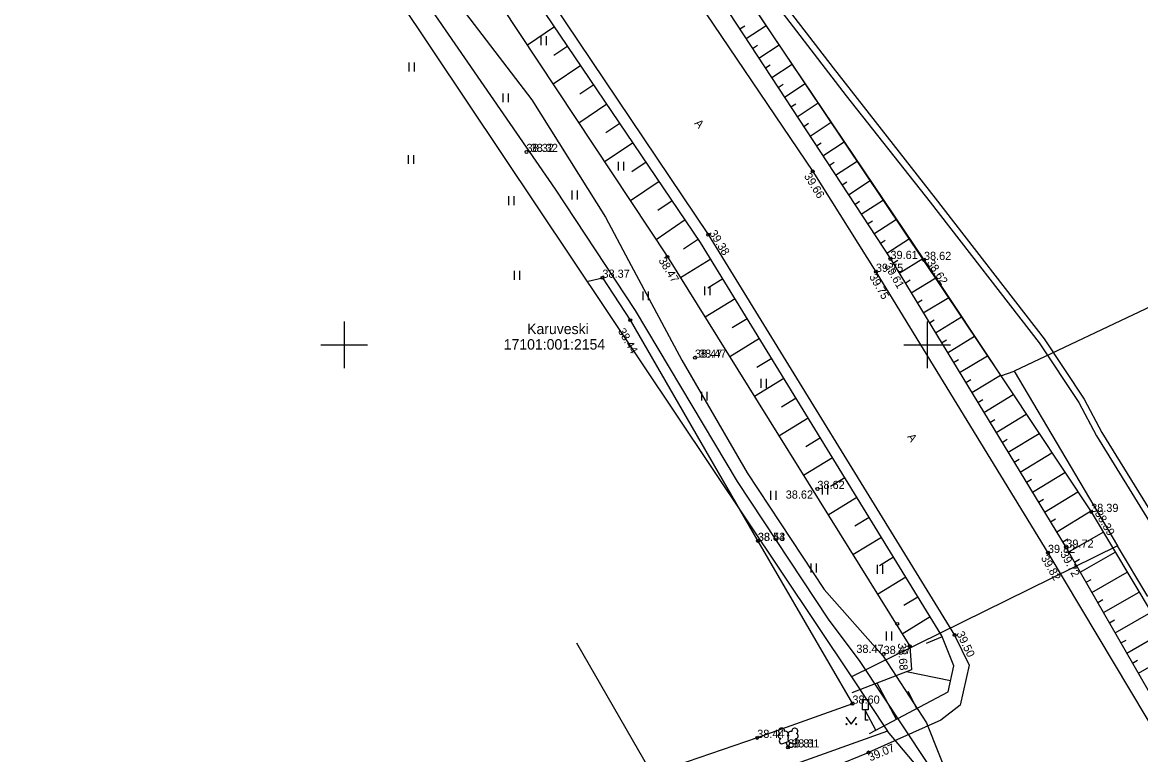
# Model space of a CAD drawing. Extents: x 627548 to 628052, y 6467984 to 6468802.
# Drawn here: x 627722.4 to 627818.3, y 6468464.9 to 6468527.7 of the extents above; entities that cross this region are included whole.
import ezdxf

# ---------------------------------------------------------------- set-up
doc = ezdxf.new("R2010")
doc.units = 0
for name, color, linetype in [('AED', 7, 'Continuous'), ('HALJASTUS', 7, 'Continuous'), ('KORGUS-EH2000', 7, 'Continuous'), ('KPKAABEL', 7, 'Continuous'), ('LIIKLUS', 7, 'Continuous'), ('MOOTKORG-EH2000', 7, 'Continuous'), ('MOOTMPUNKT', 7, 'Continuous'), ('MPKAABEL', 7, 'Continuous'), ('MPOHULIIN', 7, 'Continuous'), ('PIIR', 7, 'Continuous'), ('PUU', 7, 'Continuous'), ('RELJEEF', 7, 'Continuous'), ('SITRASS', 7, 'Continuous'), ('TEE', 7, 'Continuous'), ('VORK', 7, 'Continuous')]:
    doc.layers.add(name, color=color, linetype=linetype)

msp = doc.modelspace()

# ---------------------------------------------------------------- linework, layer by layer
at = {"layer": 'AED'}
for points in [[(627770.937, 6468505.458), (627772.148, 6468505.761), (627774.528, 6468502.126), (627785.471, 6468483.185), (627793.589, 6468469.234)], [(627793.589, 6468469.234), (627785.422, 6468466.301), (627773.403, 6468462.19), (627765.44, 6468459.471)]]:
    msp.add_lwpolyline(points, dxfattribs=at)
at = {"layer": 'HALJASTUS'}
for p, q in [((627766.874, 6468526.485), (627766.874, 6468525.724)), ((627767.329, 6468526.485), (627767.329, 6468525.724)), ((627755.548, 6468524.212), (627755.548, 6468523.45)), ((627756.003, 6468524.212), (627756.003, 6468523.45)), ((627763.616, 6468521.569), (627763.616, 6468520.808)), ((627764.071, 6468521.569), (627764.071, 6468520.808)), ((627755.481, 6468516.283), (627755.481, 6468515.522)), ((627755.936, 6468516.283), (627755.936, 6468515.522)), ((627773.488, 6468515.716), (627773.488, 6468514.955)), ((627773.943, 6468515.716), (627773.943, 6468514.955)), ((627764.09, 6468512.759), (627764.09, 6468511.998)), ((627764.545, 6468512.759), (627764.545, 6468511.998)), ((627769.513, 6468513.233), (627769.513, 6468512.472)), ((627769.968, 6468513.233), (627769.968, 6468512.472)), ((627764.576, 6468506.357), (627764.576, 6468505.595)), ((627765.031, 6468506.357), (627765.031, 6468505.595)), ((627780.911, 6468505.024), (627780.911, 6468504.263)), ((627781.366, 6468505.024), (627781.366, 6468504.263)), ((627775.626, 6468504.595), (627775.626, 6468503.833)), ((627776.081, 6468504.595), (627776.081, 6468503.833)), ((627785.745, 6468497.09), (627785.745, 6468496.329)), ((627786.2, 6468497.09), (627786.2, 6468496.329)), ((627780.643, 6468495.988), (627780.643, 6468495.227)), ((627781.098, 6468495.988), (627781.098, 6468495.227)), ((627791, 6468487.94), (627791, 6468487.179)), ((627791.455, 6468487.94), (627791.455, 6468487.179)), ((627786.556, 6468487.484), (627786.556, 6468486.723)), ((627787.011, 6468487.484), (627787.011, 6468486.723)), ((627790.013, 6468481.249), (627790.013, 6468480.488)), ((627790.468, 6468481.249), (627790.468, 6468480.488)), ((627795.71, 6468481.138), (627795.71, 6468480.376)), ((627796.165, 6468481.138), (627796.165, 6468480.376)), ((627796.474, 6468475.416), (627796.474, 6468474.655)), ((627796.929, 6468475.416), (627796.929, 6468474.655)), ((627793.019, 6468468.081), (627793.483, 6468467.474)), ((627793.483, 6468467.474), (627793.928, 6468468.081))]:
    msp.add_line(p, q, dxfattribs=at)
for centre in [(627793.081, 6468467.474), (627793.91, 6468467.474)]:
    msp.add_circle(centre, 0.055, dxfattribs=at)
at = {"layer": 'KORGUS-EH2000'}
for centre in [(627790.19, 6468514.887), (627781.22, 6468509.457), (627777.72, 6468507.557), (627774.53, 6468502.127), (627802.36, 6468475.117), (627798.51, 6468474.167), (627794.97, 6468465.057)]:
    msp.add_circle(centre, 0.125, dxfattribs=at)
at = {"layer": 'KPKAABEL'}
msp.add_lwpolyline([(627783.664, 6468533.605), (627793.043, 6468521.367), (627800.254, 6468512.234), (627809.598, 6468500.188), (627812.996, 6468495.066), (627814.512, 6468492.199), (627820.805, 6468482.012), (627827.375, 6468470.727), (627831.316, 6468464.148), (627838.215, 6468452.395), (627843.543, 6468447.449), (627852.07, 6468429.637), (627862.617, 6468434.004), (627863.434, 6468433.738), (627868.465, 6468427.605)], dxfattribs=at)
at = {"layer": 'LIIKLUS'}
for points in [[(627794.439, 6468469.559), (627794.439, 6468468.709)], [(627794.939, 6468469.559), (627794.439, 6468469.559)], [(627794.939, 6468469.559), (627794.939, 6468468.709)], [(627794.939, 6468468.709), (627794.439, 6468468.709)], [(627794.689, 6468468.709), (627794.689, 6468467.809)], [(627794.939, 6468467.809), (627794.689, 6468467.809)]]:
    msp.add_lwpolyline(points, dxfattribs=at)
at = {"layer": 'MOOTMPUNKT'}
for centre in [(627765.636, 6468516.549), (627796.852, 6468507.373), (627799.726, 6468507.289), (627772.148, 6468505.761), (627795.603, 6468506.268), (627780.081, 6468498.904), (627790.584, 6468487.647), (627814.065, 6468485.677), (627785.486, 6468483.195), (627810.358, 6468482.16), (627811.934, 6468482.612), (627797.433, 6468476.083), (627796.265, 6468473.492), (627793.589, 6468469.234), (627785.422, 6468466.301), (627788.07, 6468465.478)]:
    msp.add_circle(centre, 0.125, dxfattribs=at)
at = {"layer": 'MPKAABEL'}
msp.add_lwpolyline([(627775.609, 6468546.285), (627774.98, 6468546.789), (627774.719, 6468546.18), (627774.691, 6468545.898), (627776.109, 6468544.039), (627784.09, 6468533.941), (627791.949, 6468523.77), (627800.68, 6468512.578), (627810.039, 6468500.512), (627813.461, 6468495.352), (627814.988, 6468492.48), (627821.281, 6468482.301), (627827.852, 6468471.012), (627838.641, 6468452.75), (627843.988, 6468447.781), (627852.328, 6468430.34), (627859.234, 6468424.973)], dxfattribs=at)
at = {"layer": 'MPOHULIIN'}
msp.add_lwpolyline([(627776.772, 6468462.547), (627769.965, 6468474.421)], dxfattribs=at)
at = {"layer": 'PIIR'}
for p, q in [((627739.66, 6468596.76), (627806.32, 6468497.36)), ((627746.88, 6468541.25), (627793.5, 6468471.53)), ((627819.793, 6468503.596), (627807.45, 6468497.75)), ((627806.32, 6468497.36), (627807.45, 6468497.75)), ((627807.45, 6468497.75), (627816.33, 6468482.77)), ((627816.33, 6468482.77), (627793.5, 6468471.53)), ((627818.92, 6468478.42), (627816.33, 6468482.77)), ((627793.5, 6468471.53), (627796.61, 6468466.88)), ((627796.61, 6468466.88), (627730.27, 6468443.22)), ((627801.28, 6468461.34), (627796.61, 6468466.88))]:
    msp.add_line(p, q, dxfattribs=at)
at = {"layer": 'PUU'}
for p, q in [((627787.63, 6468465.813), (627788.075, 6468465.988)), ((627788.07, 6468465.478), (627787.895, 6468465.918)), ((627788.07, 6468465.478), (627788.25, 6468465.918)), ((627788.075, 6468465.988), (627788.515, 6468465.808)), ((627788.45, 6468465.478), (627788.07, 6468465.478))]:
    msp.add_line(p, q, dxfattribs=at)
msp.add_lwpolyline([(627788.075, 6468466.483), (627788.055, 6468466.408), (627788.055, 6468466.388), (627788.065, 6468466.358), (627788.085, 6468466.323), (627788.09, 6468466.303), (627788.075, 6468466.268), (627788.05, 6468466.218), (627788.045, 6468466.193), (627788.05, 6468466.178), (627788.06, 6468466.148), (627788.095, 6468466.088), (627788.1, 6468466.068), (627788.095, 6468466.048), (627788.08, 6468466.013), (627788.075, 6468465.988)], dxfattribs=at)
for centre, radius, start, end in [((627787.439, 6468466.481), 0.224, 111.43041, 274.49868), ((627787.513, 6468466.892), 0.256, 111.50269, 232.51731), ((627787.513, 6468466.892), 0.256, 350.48556, 111.50017), ((627787.848, 6468466.642), 0.224, 308.50412, 111.57247), ((627788.074, 6468466.245), 0.237, 66.76552, 111.50149), ((627788.311, 6468466.637), 0.225, 67.7016, 230.51262), ((627788.649, 6468466.883), 0.256, 67.6168, 188.63142), ((627788.716, 6468466.471), 0.224, 264.6183, 67.68657), ((627788.649, 6468466.883), 0.256, 306.59966, 67.61428), ((627787.544, 6468466.036), 0.237, 111.50143, 291.50036), ((627788.605, 6468466.028), 0.237, 247.61661, 67.61554)]:
    msp.add_arc(centre, radius, start, end, dxfattribs=at)
at = {"layer": 'RELJEEF'}
for p, q in [((627768.047, 6468527.281), (627765.71, 6468525.699)), ((627783.932, 6468527.108), (627784.351, 6468527.382)), ((627784.48, 6468526.272), (627786.183, 6468527.387)), ((627769.168, 6468525.625), (627767.991, 6468524.828)), ((627785.028, 6468525.435), (627785.446, 6468525.709)), ((627785.575, 6468524.598), (627787.301, 6468525.728)), ((627786.123, 6468523.762), (627786.542, 6468524.035)), ((627786.671, 6468522.925), (627788.419, 6468524.069)), ((627770.289, 6468523.969), (627767.918, 6468522.364)), ((627771.41, 6468522.312), (627770.216, 6468521.504)), ((627787.219, 6468522.088), (627787.637, 6468522.362)), ((627787.766, 6468521.252), (627789.537, 6468522.41)), ((627772.531, 6468520.656), (627770.127, 6468519.028)), ((627788.314, 6468520.415), (627788.732, 6468520.689)), ((627788.862, 6468519.578), (627790.654, 6468520.752)), ((627773.652, 6468519), (627772.442, 6468518.18)), ((627789.41, 6468518.742), (627789.828, 6468519.016)), ((627789.957, 6468517.905), (627791.772, 6468519.093)), ((627774.773, 6468517.343), (627772.335, 6468515.693)), ((627790.505, 6468517.068), (627790.923, 6468517.342)), ((627791.053, 6468516.232), (627792.89, 6468517.434)), ((627775.894, 6468515.687), (627774.667, 6468514.856)), ((627791.6, 6468515.395), (627792.019, 6468515.669)), ((627792.148, 6468514.558), (627794.007, 6468515.776)), ((627777.015, 6468514.031), (627774.543, 6468512.358)), ((627792.696, 6468513.722), (627793.114, 6468513.996)), ((627793.244, 6468512.885), (627795.125, 6468514.117)), ((627778.136, 6468512.374), (627776.892, 6468511.532)), ((627793.791, 6468512.048), (627794.21, 6468512.322)), ((627794.339, 6468511.212), (627796.243, 6468512.458)), ((627779.257, 6468510.718), (627776.752, 6468509.022)), ((627794.887, 6468510.375), (627795.305, 6468510.649)), ((627795.434, 6468509.538), (627797.361, 6468510.799)), ((627780.378, 6468509.062), (627779.114, 6468508.206)), ((627795.982, 6468508.702), (627796.4, 6468508.976)), ((627796.53, 6468507.865), (627798.478, 6468509.141)), ((627781.436, 6468507.365), (627778.835, 6468505.77)), ((627797.066, 6468507.021), (627797.493, 6468507.281)), ((627797.586, 6468506.167), (627799.639, 6468507.418)), ((627782.482, 6468505.66), (627781.187, 6468504.866)), ((627798.107, 6468505.313), (627798.534, 6468505.573)), ((627798.627, 6468504.459), (627800.747, 6468505.75)), ((627783.527, 6468503.955), (627780.949, 6468502.374)), ((627799.667, 6468502.751), (627801.853, 6468504.083)), ((627799.147, 6468503.605), (627799.574, 6468503.865)), ((627784.573, 6468502.25), (627783.289, 6468501.463)), ((627800.187, 6468501.897), (627800.614, 6468502.157)), ((627800.708, 6468501.043), (627802.96, 6468502.415)), ((627785.618, 6468500.545), (627783.063, 6468498.978)), ((627801.228, 6468500.189), (627801.655, 6468500.449)), ((627801.748, 6468499.335), (627804.066, 6468500.747)), ((627786.664, 6468498.84), (627785.392, 6468498.06)), ((627802.268, 6468498.481), (627802.695, 6468498.741)), ((627802.788, 6468497.627), (627805.173, 6468499.079)), ((627803.829, 6468495.919), (627806.28, 6468497.411)), ((627787.709, 6468497.135), (627785.177, 6468495.583)), ((627803.309, 6468496.773), (627803.736, 6468497.033)), ((627788.755, 6468495.43), (627787.495, 6468494.657)), ((627804.349, 6468495.065), (627804.776, 6468495.325)), ((627804.869, 6468494.211), (627807.386, 6468495.744)), ((627789.8, 6468493.725), (627787.292, 6468492.187)), ((627805.389, 6468493.357), (627805.817, 6468493.617)), ((627805.91, 6468492.502), (627808.493, 6468494.076)), ((627806.95, 6468490.794), (627809.599, 6468492.408)), ((627790.846, 6468492.02), (627789.597, 6468491.254)), ((627806.43, 6468491.648), (627806.857, 6468491.909)), ((627807.99, 6468489.086), (627810.706, 6468490.74)), ((627791.891, 6468490.315), (627789.406, 6468488.791)), ((627807.47, 6468489.94), (627807.897, 6468490.2)), ((627792.936, 6468488.61), (627791.7, 6468487.852)), ((627809.031, 6468487.378), (627811.812, 6468489.072)), ((627808.511, 6468488.232), (627808.938, 6468488.492)), ((627793.982, 6468486.905), (627791.52, 6468485.395)), ((627809.551, 6468486.524), (627809.978, 6468486.784)), ((627810.071, 6468485.67), (627812.919, 6468487.405)), ((627811.112, 6468483.962), (627814.025, 6468485.737)), ((627795.027, 6468485.2), (627793.802, 6468484.449)), ((627810.591, 6468484.816), (627811.019, 6468485.076)), ((627812.143, 6468482.248), (627815.1, 6468483.946)), ((627796.073, 6468483.495), (627793.634, 6468482)), ((627811.632, 6468483.108), (627812.059, 6468483.368)), ((627813.138, 6468480.514), (627816.127, 6468482.229)), ((627797.118, 6468481.79), (627795.905, 6468481.046)), ((627812.641, 6468481.381), (627813.074, 6468481.63)), ((627798.164, 6468480.085), (627795.749, 6468478.604)), ((627814.134, 6468478.779), (627817.153, 6468480.513)), ((627813.636, 6468479.647), (627814.07, 6468479.896)), ((627799.209, 6468478.38), (627798.007, 6468477.643)), ((627814.632, 6468477.912), (627815.066, 6468478.161)), ((627815.13, 6468477.045), (627818.18, 6468478.796)), ((627816.126, 6468475.31), (627819.206, 6468477.079)), ((627800.255, 6468476.675), (627797.863, 6468475.208)), ((627815.628, 6468476.178), (627816.061, 6468476.427)), ((627817.121, 6468473.576), (627820.233, 6468475.362)), ((627801.287, 6468474.963), (627799.909, 6468474.409)), ((627816.624, 6468474.443), (627817.057, 6468474.692)), ((627818.117, 6468471.841), (627821.26, 6468473.645)), ((627817.619, 6468472.709), (627818.053, 6468472.958)), ((627802.009, 6468471.184), (627798.225, 6468471.976)), ((627797.357, 6468467.891), (627795.715, 6468471.006)), ((627799.127, 6468468.824), (627798.36, 6468470.278)), ((627795.588, 6468466.959), (627794.713, 6468468.62))]:
    msp.add_line(p, q, dxfattribs=at)
for points in [[(627795.053, 6468466.676), (627801.811, 6468470.239), (627802.282, 6468472.489), (627801.253, 6468475.047), (627780.564, 6468508.787), (627754.569, 6468547.196), (627739.327, 6468568.568), (627737.903, 6468570.271), (627734.898, 6468569.029), (627730.198, 6468567.042)], [(627730.198, 6468567.042), (627735.301, 6468567.584), (627736.992, 6468567.054), (627752.348, 6468545.88), (627777.723, 6468507.555), (627798.509, 6468474.17), (627798.646, 6468472.139), (627793.544, 6468470.167)], [(627773.759, 6468549.461), (627771.296, 6468547.152), (627771.109, 6468545.291), (627781.198, 6468531.285), (627796.852, 6468507.373), (627811.934, 6468482.612), (627825.927, 6468458.237), (627843.642, 6468425.485), (627854.711, 6468402.298), (627862.101, 6468385.395), (627866.289, 6468377.389), (627871.184, 6468377.936)], [(627772.366, 6468547.143), (627782.438, 6468532.945), (627799.726, 6468507.289), (627814.065, 6468485.677), (627830.011, 6468459.01), (627845.394, 6468427.254), (627850.56, 6468416.941), (627856.095, 6468405.157), (627864.813, 6468385.745), (627868.21, 6468378.879), (627870.923, 6468379.118)]]:
    msp.add_lwpolyline(points, dxfattribs=at)
at = {"layer": 'SITRASS'}
for points in [[(627757.217, 6468532.631), (627766.085, 6468521.026), (627772.396, 6468510.946), (627774.395, 6468507.251), (627778.965, 6468498.694), (627784.571, 6468489.044), (627791.177, 6468479.022), (627796.223, 6468473.32), (627799.931, 6468467.58), (627802.003, 6468462.412), (627804.987, 6468458.791), (627809.717, 6468452.583), (627813.499, 6468446.21), (627816.609, 6468440.925), (627819.703, 6468435.299), (627820.118, 6468434.673)], [(627757.269, 6468529.067), (627768.1, 6468513.354), (627774.946, 6468502.943), (627783.7, 6468488.286), (627791.516, 6468476.471), (627794.222, 6468472.86), (627799.922, 6468464.28), (627804.258, 6468458.3), (627808.24, 6468452.254), (627816.937, 6468435.872), (627827.445, 6468415.491), (627836.355, 6468397.304), (627844.956, 6468379.511), (627852.286, 6468362.282), (627856.189, 6468352.574), (627857.741, 6468350.531), (627858.742, 6468350.866)]]:
    msp.add_lwpolyline(points, dxfattribs=at)
at = {"layer": 'TEE'}
for points in [[(627678.512, 6468625.342), (627686.437, 6468627.071), (627688.377, 6468627.547), (627694.212, 6468628.779), (627697.947, 6468628.287), (627705.762, 6468618.126), (627714.785, 6468606.184), (627724.497, 6468592.392), (627727.994, 6468587.234), (627755.631, 6468547.562), (627781.22, 6468509.462), (627802.357, 6468475.114), (627803.599, 6468472.534), (627802.841, 6468469.11), (627801.159, 6468467.815), (627794.971, 6468465.055)], [(627773.875, 6468550.47), (627771.331, 6468547.778), (627770.184, 6468544.969), (627779.724, 6468530.382), (627790.194, 6468514.89), (627795.603, 6468506.268), (627810.358, 6468482.16), (627820.252, 6468465.61), (627824.787, 6468457.176), (627842.022, 6468424.68), (627853.219, 6468402.014), (627861.194, 6468384.862), (627867.233, 6468371.168), (627873.073, 6468356.381), (627889.258, 6468318.908), (627892.446, 6468311.434), (627896.87, 6468301.517), (627899.405, 6468301.54), (627901.626, 6468302.361)], [(627765.165, 6468459.007), (627766.223, 6468457.303), (627768.784, 6468456.128), (627770.445, 6468455.699), (627773.709, 6468456.834), (627786.129, 6468461.455), (627794.971, 6468465.055)]]:
    msp.add_lwpolyline(points, dxfattribs=at)
at = {"layer": 'VORK'}
for p, q in [((627750, 6468502), (627750, 6468498)), ((627800, 6468502), (627800, 6468498)), ((627748, 6468500), (627752, 6468500)), ((627798, 6468500), (627802, 6468500))]:
    msp.add_line(p, q, dxfattribs=at)

# ---------------------------------------------------------------- texts
at = {"layer": 'KORGUS-EH2000'}
for s, p in [('38.32', (627765.986, 6468516.549)), ('38.47', (627780.431, 6468498.904)), ('38.62', (627787.87, 6468486.82)), ('38.47', (627793.926, 6468473.592)), ('38.81', (627788.42, 6468465.478))]:
    msp.add_text(s, height=0.7, dxfattribs=at).set_placement(p)
for s, rotation, p in [(' 39.66', 301.9417, (627789.275, 6468514.702)), (' 39.38', 301.60722, (627781.149, 6468509.818)), (' 38.47', 301.90701, (627776.79, 6468507.471)), ('39.61', 300.31074, (627796.297, 6468506.785)), ('38.62', 303.90974, (627799.944, 6468507.044)), ('39.75', 300.20437, (627795.002, 6468505.855)), (' 38.44', 300.28918, (627773.319, 6468501.42)), ('38.39', 300.71623, (627814.346, 6468485.576)), ('39.82', 300.35535, (627809.73, 6468481.732)), ('39.72', 298.70526, (627811.39, 6468482.071)), (' 39.50', 295.70595, (627802.375, 6468475.486)), (' 38.68', 273.85901, (627797.471, 6468474.668)), (' 39.07', 22.74559, (627794.887, 6468464.179))]:
    msp.add_text(s, height=0.7, rotation=rotation, dxfattribs=at).set_placement(p)
at = {"layer": 'MOOTKORG-EH2000'}
for s, p in [('38.32', (627765.636, 6468516.549)), ('39.61', (627796.852, 6468507.373)), ('38.62', (627799.726, 6468507.289)), ('39.75', (627795.603, 6468506.268)), ('38.37', (627772.148, 6468505.761)), ('38.47', (627780.081, 6468498.904)), ('38.62', (627790.584, 6468487.647)), ('38.39', (627814.065, 6468485.677)), ('38.44', (627785.471, 6468483.185)), ('38.53', (627785.486, 6468483.195)), ('39.82', (627810.358, 6468482.16)), ('39.72', (627811.934, 6468482.612)), ('38.47', (627796.265, 6468473.492)), ('38.60', (627793.589, 6468469.234)), ('38.44', (627785.422, 6468466.301)), ('38.81', (627788.07, 6468465.478))]:
    msp.add_text(s, height=0.7, dxfattribs=at).set_placement(p)
at = {"layer": 'PIIR'}
for s, p in [('Karuveski', (627765.687, 6468500.931)), ('17101:001:2154', (627763.68, 6468499.6))]:
    msp.add_text(s, height=0.9, dxfattribs=at).set_placement(p)
at = {"layer": 'TEE'}
for rotation, p in [(311.96552, (627779.995, 6468518.98)), (303.01855, (627798.262, 6468492.128))]:
    msp.add_text('A', height=0.7, rotation=rotation, dxfattribs=at).set_placement(p)

doc.saveas('drawing.dxf')
